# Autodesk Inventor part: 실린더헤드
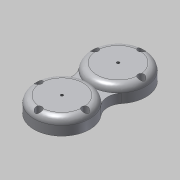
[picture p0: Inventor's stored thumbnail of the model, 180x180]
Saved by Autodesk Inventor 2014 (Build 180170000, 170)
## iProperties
Created: 2016-11
Part Number: 실린더헤드
Material: 알루미늄 6061
Document SubType Name: Modeling
Designer: mduedu
Density: 2.71 g/cm^3
Mass: 538.448 g
Surface Area: 423.673 cm^2
Volume: 198.689 cm^3
Appearance: 알루미늄 - 평지
Author: mduedu
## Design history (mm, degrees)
sketch "스케치1"
  geometry: C1 r 42 at (0, 0); 1 further point
  constraints: 1 centre point, 1 coincident
  dimensions: "d0" = 84 diameter of C1
extrude "돌출1" new body sketch "스케치1" distance "d1" = 24; taper "d2" = 0 deg
fillet "모깎기1" dims "d3" = 10
sketch "스케치2"
  geometry: C1 r 30 at (0, 0); 1 further point
  constraints: 1 centre point, 1 coincident
  dimensions: "d4" = 60 diameter of C1
extrude "돌출2" join sketch "스케치2" distance "d5" = 5; taper "d6" = 0 deg
sketch "스케치3"
  geometry: C1 r 25 at (0, 0); 1 further point
  constraints: 1 centre point, 1 coincident
  dimensions: "d7" = 50 diameter of C1
extrude "돌출3" cut sketch "스케치3" distance "d8" = 20; taper "d9" = 0 deg
hole "구멍1" diameter "d12" = 4.134; stored, may be unused: countersink angle "d16" = 90 deg, drill point angle "d18" = 118 deg; dims "d10" = 10, "d11" = 10, "d13" = 6, "d14" = 4, "d15" = 2, "d17" = 8
chamfer "모따기1" distance "d19" = 1; stored, may be unused: second distance "d20" = 2, angle "d21" = 45 deg
fillet "모깎기2" dims "d22" = 3
sketch "스케치4"
  geometry: C1 r 17.5 at (0, 0); 1 further point
  constraints: 1 centre point, 1 coincident
  dimensions: "d23" = 35 diameter of C1
extrude "돌출4" cut sketch "스케치4" distance "d24" = 2; taper "d25" = 0 deg
fillet "모깎기3" dims "d26" = 0.5
sketch "스케치5" dims "d32" = 70
  geometry: C1 r 5 at (0, 35); 3 further points
  constraints: 2 coincident, 2 vertical alignment, 1 centre point, 2 other
  dimensions: "d33" = 10 diameter of C1
extrude "돌출5" cut sketch "스케치5" distance "d34" = 10; taper "d35" = 0 deg
sketch "스케치6"
  geometry: A1 r 35 centre (0, -35) between (0, 0) and (-35, -35); 2 further points
  constraints: 3 point on circle, 2 horizontal alignment, 1 centre point, 1 coincident, 1 vertical alignment
  dimensions: "d39" = 70 diameter of A1
hole "구멍3" sketch "스케치6" at (0, 0), (-35, -35), (35, -35) diameter "d57" = 5.5; stored, may be unused: countersink angle "d61" = 90 deg, drill point angle "d63" = 118 deg; dims "d58" = 6, "d59" = 4, "d60" = 2, "d62" = 8
chamfer "모따기2" distance "d54" = 5; stored, may be unused: second distance "d55" = 2, angle "d56" = 30 deg
node "작업 평면1"
sketch "스케치8"
  geometry: L1 (0, 85)-(0, 0); A1 r 42 centre (0, 85) between (-32.469, 58.358) and (32.469, 58.358) reference; A2 r 42 centre (0, 0) between (-32.469, 26.642) and (32.469, 26.642) reference; A3 r 25 centre (51.795, 42.5) between (32.469, 26.642) and (32.469, 58.358); A4 r 25 centre (-51.795, 42.5) between (-32.469, 58.358) and (-32.469, 26.642); A5 r 25 centre (-51.795, 42.5) between (-32.469, 26.642) and (-32.469, 58.358); A6 r 25 centre (51.795, 42.5) between (32.469, 58.358) and (32.469, 26.642); A7 r 42 centre (0, 85) between (-32.469, 58.358) and (32.469, 58.358); A8 r 42 centre (0, 0) between (32.469, 26.642) and (-32.469, 26.642); 1 further point
  constraints: 16 point on circle, 6 centre point, 2 coincident, 2 end point, 2 tangent, 1 symmetric about line, 1 vertical, 1 other
  dimensions: "d65" = 50 diameter of A3
extrude "돌출6" join sketch "스케치8" distance "d67" = 14; taper "d68" = 0 deg
node "솔리드1"
pattern_circular "원형 패턴1" dims angle "d37" = 360 deg
mirror "대칭1"
other parameters: "d64" = 42.5
